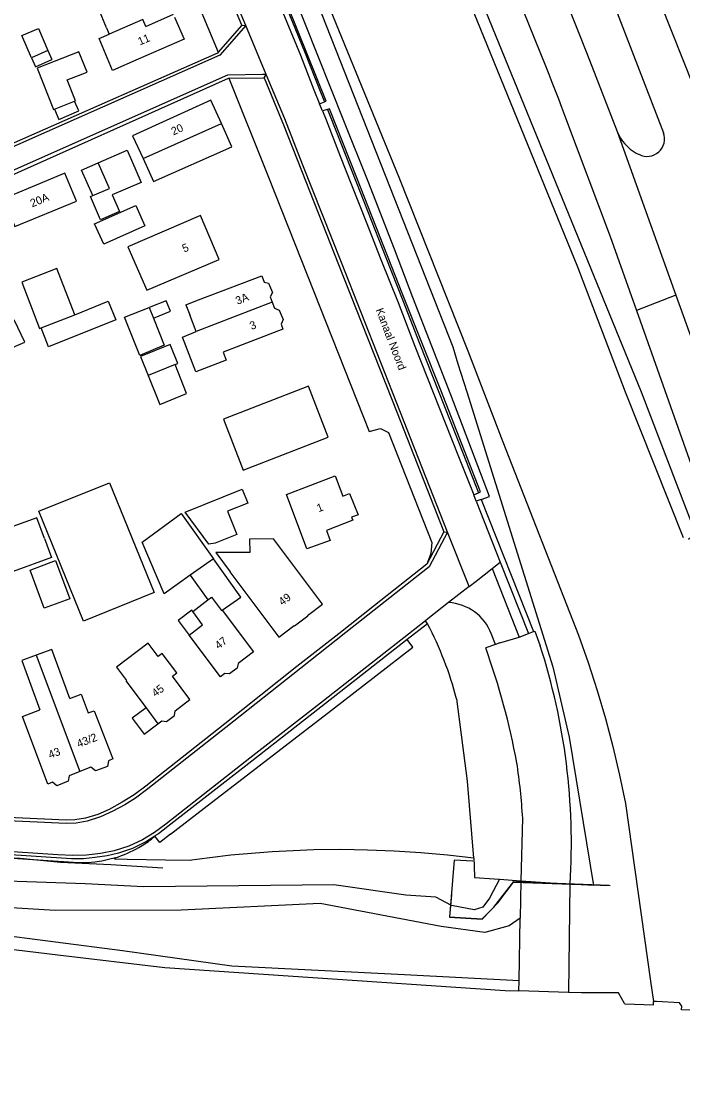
# Model space of a CAD drawing. Extents: x 194485 to 197793, y 468269 to 470822.
# Drawn here: x 195261.5 to 195360.6, y 469144.3 to 469305.5 of the extents above; entities that cross this region are included whole.
import ezdxf

# ---------------------------------------------------------------- set-up
doc = ezdxf.new("R2010")
doc.units = 0
for name, color, linetype in [('BGT begrenzing kruinlijn', 7, 'Continuous'), ('BGT grensvlak begroeid terreindeel', 7, 'Continuous'), ('BGT grensvlak begroeid terreindeel LR', 7, 'Continuous'), ('BGT grensvlak gebouwinstallatie plus 1', 7, 'Continuous'), ('BGT grensvlak onbegroeid terreindeel', 7, 'Continuous'), ('BGT grensvlak overbruggingsdeel plus 1', 7, 'Continuous'), ('BGT grensvlak overig bouwwerk uitbreiding populatie', 7, 'Continuous'), ('BGT grensvlak pand op maaiveld', 7, 'Continuous'), ('BGT grensvlak pand op maaiveld LR', 7, 'Continuous'), ('BGT grensvlak vegetatieobject', 7, 'Continuous'), ('BGT grensvlak waterdeel', 7, 'Continuous'), ('BGT grensvlak wegdeel', 7, 'Continuous'), ('BGT lijnelement scheiding hek', 7, 'Continuous'), ('BGT tekst huisnummerreeks', 7, 'Continuous'), ('BGT tekst openbare ruimte label weg', 7, 'Continuous')]:
    doc.layers.add(name, color=color, linetype=linetype)

msp = doc.modelspace()

# ---------------------------------------------------------------- linework, layer by layer
at = {"layer": 'BGT begrenzing kruinlijn'}
msp.add_lwpolyline([(195333.17, 469176.92), (195331.68, 469174.1), (195330.67, 469172.73), (195329.38, 469172.32), (195325.94, 469172.96), (195323.63, 469174.22), (195319.11, 469174.55), (195308.33, 469176.06), (195279.82, 469175.77), (195271.02, 469176.24), (195250.48, 469176.91), (195218.26, 469179.64), (195172.02, 469183.73), (195139.62, 469186.43), (195110.38, 469187.78), (195083.73, 469188.2), (195047.24, 469190.12), (195024.68, 469191.98), (195021.62, 469193.6)], dxfattribs=at)
at = {"layer": 'BGT grensvlak begroeid terreindeel'}
for p, q in [((195269.27, 469179.41), (195145.74, 469187.55)), ((195333.17, 469176.92), (195336.35, 469176.7))]:
    msp.add_line(p, q, dxfattribs=at)
for points in [[(195249.52, 469422.51), (195254.02, 469415.15), (195263.96, 469398.93), (195268.08, 469392.21), (195276.98, 469375.91), (195284.84, 469359.67), (195304.44, 469311.84), (195326.14, 469256.74), (195326.93, 469254.23), (195328.26, 469250), (195341.19, 469208.79), (195343.63, 469198.23), (195347.26, 469175.96), (195343.77, 469176.2)], [(195275.54, 469180.15), (195274.52, 469179.86), (195273.49, 469179.65), (195272.44, 469179.49), (195271.39, 469179.4), (195270.33, 469179.37), (195269.27, 469179.41)], [(195286.62, 469179.73), (195283.08, 469179.8), (195277.33, 469179.9), (195275.42, 469179.94), (195275.54, 469180.15)], [(195305.33, 469181.31), (195302.2, 469181.2), (195299.08, 469181.03), (195295.95, 469180.8), (195292.84, 469180.51), (195289.73, 469180.15), (195286.62, 469179.73)], [(195329.33, 469180.06), (195325.34, 469180.52), (195321.35, 469180.88), (195317.35, 469181.15), (195313.35, 469181.3), (195309.34, 469181.36), (195305.33, 469181.31)], [(195329.33, 469180.06), (195329.36, 469178.93), (195329.44, 469177.17), (195332.35, 469176.97), (195333.17, 469176.92)]]:
    msp.add_lwpolyline(points, dxfattribs=at)
at = {"layer": 'BGT grensvlak begroeid terreindeel LR'}
msp.add_line((195280.95, 469182.93), (195281.47, 469183.4), dxfattribs=at)
for points in [[(195230.64, 469478.15), (195238.04, 469470.16), (195245.24, 469462.38), (195250.08, 469456.71), (195257.38, 469448.07), (195272.68, 469426.93), (195291.77, 469397.28), (195298.55, 469383.89), (195299.68, 469381.45), (195303.16, 469373.94), (195306.08, 469367.63), (195317.89, 469339.41), (195320.66, 469332.62), (195354.4, 469250), (195362.58, 469228.77), (195361.51, 469227.88)], [(195329.33, 469180.06), (195328.34, 469191.65), (195326.74, 469203.97)]]:
    msp.add_lwpolyline(points, dxfattribs=at)
for centre, radius, start, end in [((195274.31, 469190.16), 54.21, 14.7543, 27.5622), ((195270.44, 469196.67), 17.29, 287.1559, 299.8436), ((195270.4, 469196.75), 17.39, 299.8457, 307.3814)]:
    msp.add_arc(centre, radius, start, end, dxfattribs=at)
at = {"layer": 'BGT grensvlak gebouwinstallatie plus 1'}
for p, q in [((195265.43, 469301.17), (195266.01, 469299.82)), ((195269.44, 469261.56), (195274.45, 469263.59)), ((195274.45, 469263.59), (195275.61, 469260.8)), ((195275.61, 469260.8), (195265.53, 469256.75)), ((195265.53, 469256.75), (195264.4, 469259.61)), ((195286.78, 469222.53), (195289.43, 469218.81)), ((195280.15, 469202.6), (195278.08, 469201.05)), ((195278.08, 469201.05), (195279.86, 469198.67)), ((195279.86, 469198.67), (195281.93, 469200.21))]:
    msp.add_line(p, q, dxfattribs=at)
for points in [[(195262.95, 469300.11), (195263.53, 469298.76), (195266.01, 469299.82)], [(195266.4, 469292.4), (195267.07, 469290.86), (195270.04, 469292.16), (195269.42, 469293.58)], [(195272.14, 469279.43), (195270.48, 469283.27), (195272.98, 469284.35)], [(195284.49, 469254.09), (195284.9, 469254.25), (195283.75, 469257.11), (195279.31, 469255.33), (195280.46, 469252.47)], [(195285.99, 469231.96), (195294.56, 469235.41), (195295.41, 469233.32), (195292.38, 469232.13), (195293.75, 469228.64), (195290.51, 469227.31), (195289.56, 469227.15), (195285.99, 469231.96)], [(195291.57, 469217.26), (195294.34, 469219.24), (195290.24, 469224.99)], [(195266.57, 469224.7), (195268.71, 469218.98), (195264.88, 469217.55), (195262.74, 469223.27), (195266.57, 469224.7)], [(195287.14, 469217.07), (195287, 469217.26), (195284.96, 469215.71), (195286.61, 469213.54)]]:
    msp.add_lwpolyline(points, dxfattribs=at)
at = {"layer": 'BGT grensvlak onbegroeid terreindeel'}
for points in [[(195277.66, 469332.39), (195279.61, 469327.91), (195282.53, 469320.97), (195285.35, 469314.28), (195287.86, 469308.33), (195290.98, 469300.92)], [(195292.54, 469297.03), (195298.41, 469282.44), (195302.49, 469272.09), (195313.61, 469244.08), (195315.3, 469244.52), (195316.49, 469243.92), (195322.99, 469227.43), (195322.84, 469225.79), (195322.27, 469224.15)], [(195336.26, 469171.07), (195334.6, 469169.94), (195330.96, 469168.94), (195324.39, 469169.84), (195306.28, 469173.3), (195285.39, 469172.29), (195266.49, 469172.21), (195242.61, 469173.69), (195217.64, 469175.65), (195191.44, 469178.72), (195175.95, 469179.92), (195158.29, 469182.07), (195146.14, 469183.55), (195135.37, 469183.77), (195129.51, 469183.87)], [(195336.11, 469161.69), (195318.89, 469162.6), (195293.02, 469163.89), (195276.63, 469166.21), (195256.46, 469168.77), (195245.24, 469170.07), (195243.81, 469170.16), (195230.31, 469171.25), (195224.23, 469171.64), (195215.36, 469172.48), (195208.35, 469172.93), (195181.26, 469175.57), (195174.18, 469176.35), (195167.76, 469177.15), (195162.5, 469177.71), (195150.36, 469179.4), (195142.78, 469179.86), (195129.29, 469179.89)], [(195351.93, 469158.31), (195351.96, 469158.26), (195356.25, 469158.08), (195356.28, 469158.59)], [(195360.49, 469157.36), (195360.51, 469157.91), (195360.17, 469158.4), (195356.71, 469158.57), (195356.28, 469158.59)]]:
    msp.add_lwpolyline(points, dxfattribs=at)
at = {"layer": 'BGT grensvlak overbruggingsdeel plus 1'}
msp.add_line((195368.91, 469156.95), (195360.49, 469157.36), dxfattribs=at)
at = {"layer": 'BGT grensvlak overig bouwwerk uitbreiding populatie'}
for p, q in [((195283.16, 469263.67), (195280.62, 469262.66)), ((195283.79, 469262.1), (195283.16, 469263.67)), ((195281.25, 469261.08), (195283.79, 469262.1))]:
    msp.add_line(p, q, dxfattribs=at)
at = {"layer": 'BGT grensvlak pand op maaiveld'}
for p, q in [((195274.19, 469304.59), (195273.04, 469307.38)), ((195261.52, 469303.44), (195264.01, 469304.51)), ((195264.01, 469304.51), (195265.43, 469301.17)), ((195274.19, 469304.59), (195274.61, 469303.64)), ((195262.95, 469300.11), (195261.52, 469303.44)), ((195265.43, 469301.17), (195262.95, 469300.11)), ((195266.4, 469292.4), (195269.42, 469293.58)), ((195266.24, 469292.34), (195266.4, 469292.4)), ((195286.11, 469263.08), (195288.02, 469263.81)), ((195280.62, 469262.66), (195281.25, 469261.08)), ((195286.11, 469263.08), (195286.69, 469261.56)), ((195264.4, 469259.61), (195269.44, 469261.56)), ((195281.25, 469261.08), (195282.87, 469257)), ((195287.68, 469259.04), (195286.69, 469261.56)), ((195264.17, 469259.52), (195264.4, 469259.61)), ((195300.67, 469259.4), (195291.69, 469255.95)), ((195282.87, 469257), (195279.21, 469255.48)), ((195284.49, 469254.09), (195280.46, 469252.47)), ((195285.41, 469231.78), (195290.24, 469224.99)), ((195290.24, 469224.99), (195286.78, 469222.53)), ((195294.23, 469225.93), (195290.61, 469225.9)), ((195287.14, 469217.07), (195289.43, 469218.81)), ((195280.15, 469202.6), (195281.93, 469200.21))]:
    msp.add_line(p, q, dxfattribs=at)
for points in [[(195284.43, 469306.17), (195285.87, 469302.9), (195278.97, 469299.89)], [(195278.97, 469299.89), (195275.13, 469298.21), (195273.12, 469302.98), (195274.61, 469303.64)], [(195269.42, 469293.58), (195269.56, 469293.64), (195268.33, 469296.78), (195271.29, 469297.93), (195270.08, 469301.01), (195263.81, 469298.54), (195266.24, 469292.34)], [(195291.44, 469290.24), (195289.87, 469293.74), (195278.12, 469288.42), (195279.69, 469284.98)], [(195279.69, 469284.98), (195281.27, 469281.54), (195293.02, 469286.74), (195291.44, 469290.24)], [(195272.98, 469284.35), (195277.32, 469286.23), (195279.39, 469281.42), (195275.05, 469279.55), (195276.14, 469277.05), (195273.29, 469275.82), (195271.8, 469279.28), (195272.14, 469279.43)], [(195272.14, 469279.43), (195274.64, 469280.51), (195272.98, 469284.35)], [(195267.97, 469282.78), (195258.73, 469278.95), (195260.45, 469274.79), (195269.69, 469278.62), (195267.97, 469282.78)], [(195272.43, 469275.22), (195278.59, 469277.95), (195279.95, 469274.88), (195273.8, 469272.15), (195272.43, 469275.22)], [(195277.39, 469271.77), (195280.26, 469265.23), (195291.1, 469269.86), (195288.32, 469276.45), (195277.39, 469271.77)], [(195269.44, 469261.56), (195266.76, 469268.48), (195261.49, 469266.44), (195264.17, 469259.52)], [(195288.02, 469263.81), (195297.52, 469267.42), (195297.87, 469266.46), (195298.52, 469266.31), (195299.13, 469264.88), (195298.78, 469264.23), (195299.08, 469263.48)], [(195279.21, 469255.48), (195276.93, 469261.19), (195280.62, 469262.66)], [(195299.08, 469263.48), (195299.43, 469262.58), (195300.12, 469262.27), (195300.71, 469260.87), (195300.42, 469260.16), (195300.67, 469259.4)], [(195259.4, 469256.37), (195261.93, 469257.47), (195260.36, 469260.8)], [(195291.69, 469255.95), (195292.15, 469254.77), (195287.63, 469253.01), (195285.6, 469258.22), (195287.68, 469259.04)], [(195280.46, 469252.47), (195282.2, 469248.12), (195286.23, 469249.74), (195284.49, 469254.09)], [(195291.76, 469245.91), (195294.71, 469238.27), (195307.48, 469243.21), (195304.52, 469250.84), (195291.76, 469245.91)], [(195264.06, 469232.14), (195274.67, 469236.38), (195281.38, 469219.93), (195270.77, 469215.64), (195264.06, 469232.14)], [(195301.2, 469234.62), (195308.51, 469237.42), (195309.65, 469234.35), (195310.67, 469234.77), (195311.94, 469231.58), (195310.95, 469231.24), (195311.14, 469230.76), (195307.21, 469229.24), (195307.74, 469227.73), (195304.25, 469226.47), (195301.2, 469234.62)], [(195286.78, 469222.53), (195282.85, 469219.73), (195279.54, 469227.46), (195285.41, 469231.78)], [(195264.9, 469228.01), (195263.77, 469231.14), (195257.07, 469228.7)], [(195264.9, 469228.01), (195265.94, 469225.16), (195260.22, 469223.08)], [(195290.61, 469225.9), (195292.74, 469223.03), (195292.7, 469223), (195300.05, 469213.23), (195302.37, 469214.98), (195302.41, 469214.91), (195304.39, 469216.4), (195304.34, 469216.47), (195306.63, 469218.19), (195299.27, 469227.98), (195295.67, 469227.92), (195295.7, 469225.94), (195294.23, 469225.93)], [(195289.43, 469218.81), (195289.97, 469219.21), (195291.48, 469217.21), (195291.57, 469217.27), (195291.57, 469217.26)], [(195291.57, 469217.26), (195296.26, 469211.04), (195293.94, 469209.29), (195293.83, 469208.58), (195292.67, 469207.7), (195291.95, 469207.79), (195291.3, 469207.29), (195286.61, 469213.54)], [(195286.61, 469213.54), (195288.63, 469215.07), (195287.14, 469217.07)], [(195281.93, 469200.21), (195282.53, 469200.67), (195283.23, 469200.57), (195284.41, 469201.47), (195284.5, 469202.16), (195286.72, 469203.85), (195284.12, 469207.38), (195284.75, 469207.85), (195282.57, 469210.78), (195281.95, 469210.31), (195280.46, 469212.32), (195275.71, 469208.74)], [(195263.65, 469210.51), (195261.5, 469209.72), (195264.2, 469202.3)], [(195268.7, 469204.01), (195266.02, 469211.37), (195263.65, 469210.51)], [(195275.71, 469208.74), (195277.21, 469206.73), (195277.12, 469206.66), (195280.15, 469202.6)], [(195268.7, 469204.01), (195270.4, 469204.66), (195271.45, 469201.86), (195272.36, 469202.18), (195275.18, 469194.97), (195274.53, 469194.66), (195274.35, 469193.84), (195272.55, 469193.2), (195271.88, 469193.72), (195270.23, 469193.08)], [(195270.23, 469193.08), (195268.59, 469192.44), (195268.46, 469191.62), (195266.77, 469190.94), (195266.11, 469191.49), (195265.42, 469191.18), (195261.62, 469201.3), (195264.2, 469202.3)]]:
    msp.add_lwpolyline(points, dxfattribs=at)
at = {"layer": 'BGT grensvlak pand op maaiveld LR'}
for p, q in [((195279.64, 469305.85), (195274.61, 469303.64)), ((195280.1, 469304.81), (195279.64, 469305.85)), ((195280.1, 469304.81), (195284.28, 469306.65)), ((195279.69, 469284.98), (195291.44, 469290.24)), ((195299.08, 469263.48), (195287.68, 469259.04)), ((195263.65, 469210.51), (195270.23, 469193.08))]:
    msp.add_line(p, q, dxfattribs=at)
at = {"layer": 'BGT grensvlak vegetatieobject'}
for p, q in [((195330.43, 469233.87), (195338.27, 469214.05)), ((195333.29, 469224.47), (195337.52, 469213.77)), ((195288.88, 469187.6), (195301.02, 469196.94)), ((195283.8, 469183.68), (195288.88, 469187.6))]:
    msp.add_line(p, q, dxfattribs=at)
for points in [[(195299.82, 469311.02), (195300.55, 469309.29), (195304.03, 469300.77), (195306.07, 469295.58), (195306.91, 469293.5)], [(195307.36, 469292.37), (195307.88, 469291.08), (195310, 469285.66), (195311.72, 469281.34), (195313.92, 469275.77), (195316.12, 469270.17), (195318.68, 469263.7), (195321.21, 469257.14), (195327.68, 469240.85), (195330.04, 469234.87)], [(195301.02, 469196.94), (195307.97, 469202.29), (195314.61, 469207.4), (195320.18, 469211.71), (195319.31, 469212.85)], [(195283.8, 469183.68), (195282.2, 469182.45), (195281.47, 469183.4)]]:
    msp.add_lwpolyline(points, dxfattribs=at)
at = {"layer": 'BGT grensvlak waterdeel'}
for points in [[(195297.94, 469382.06), (195300.96, 469375.28), (195310.75, 469352.34), (195344.87, 469268.75), (195352.02, 469250), (195360.73, 469228.16)], [(195297.94, 469382.06), (195300.96, 469375.28), (195310.75, 469352.34), (195344.87, 469268.75), (195352.02, 469250), (195360.73, 469228.16)], [(195279.93, 469373.84), (195286.57, 469359.56), (195296.2, 469336.38), (195307.3, 469308.43), (195318.05, 469282.21), (195328.42, 469256.17), (195333.66, 469242.5), (195345.03, 469213.53)], [(195345.03, 469213.53), (195346.48, 469209.41), (195347.82, 469205.24), (195349.05, 469201.04), (195350.17, 469196.81), (195351.17, 469192.55), (195352.06, 469188.27)], [(195352.06, 469188.27), (195355.8, 469161.65), (195356.28, 469158.59)]]:
    msp.add_lwpolyline(points, dxfattribs=at)
at = {"layer": 'BGT grensvlak wegdeel'}
for p, q in [((195312.27, 469368.3), (195340.06, 469298.87)), ((195357.3, 469308.25), (195362.29, 469295.8)), ((195294.51, 469305), (195290.98, 469300.92)), ((195294.51, 469305), (195295.09, 469304.96)), ((195298.18, 469297.6), (195295.09, 469304.96)), ((195297.84, 469297.08), (195298.18, 469297.6)), ((195292.54, 469297.03), (195297.84, 469297.08)), ((195306.17, 469293.18), (195306.91, 469293.5)), ((195306.59, 469292.14), (195306.17, 469293.18)), ((195307.36, 469292.37), (195306.59, 469292.14)), ((195342.93, 469291.49), (195349.77, 469273.29)), ((195350.81, 469289.04), (195359.63, 469264.5)), ((195353.67, 469285.78), (195354.11, 469285.62)), ((195349.77, 469273.29), (195353.71, 469262.19)), ((195359.63, 469264.5), (195353.71, 469262.19)), ((195359.63, 469264.5), (195362.28, 469257.14)), ((195329.31, 469234.54), (195330.04, 469234.87)), ((195329.68, 469233.6), (195329.31, 469234.54)), ((195330.43, 469233.87), (195329.68, 469233.6)), ((195329.68, 469233.6), (195333.29, 469224.47)), ((195324.81, 469229.01), (195322.27, 469224.15)), ((195324.81, 469229.01), (195325.37, 469228.98)), ((195328.59, 469220.8), (195325.37, 469228.98)), ((195329.65, 469221.63), (195332.08, 469223.53)), ((195332.08, 469223.53), (195333.29, 469224.47)), ((195332.08, 469223.53), (195336.13, 469213.24)), ((195328.59, 469220.8), (195325.52, 469218.4)), ((195328.59, 469220.8), (195329.65, 469221.63)), ((195325.52, 469218.4), (195322.41, 469215.95)), ((195322.04, 469215.67), (195313.26, 469208.75)), ((195322.41, 469215.95), (195322.04, 469215.67)), ((195322.37, 469215.24), (195322.04, 469215.67)), ((195322.37, 469215.24), (195319.31, 469212.85)), ((195332.56, 469212.13), (195331.93, 469213.75)), ((195336.13, 469213.24), (195337.52, 469213.77)), ((195337.52, 469213.77), (195338.27, 469214.05)), ((195338.27, 469214.05), (195338.46, 469214.12)), ((195338.46, 469214.12), (195339.28, 469211.91)), ((195332.56, 469212.13), (195331.1, 469211.61)), ((195333.24, 469212.38), (195332.56, 469212.13)), ((195333.24, 469212.38), (195336.13, 469213.24)), ((195313.26, 469208.75), (195306.75, 469203.68)), ((195306.75, 469203.68), (195295.7, 469195.08)), ((195295.7, 469195.08), (195283.1, 469185.2)), ((195283.1, 469185.2), (195281.4, 469183.93)), ((195336.64, 469186.08), (195336.35, 469176.7)), ((195281.4, 469183.93), (195279.63, 469182.83)), ((195266.9, 469180.58), (195246.93, 469181.88)), ((195277.57, 469181.88), (195275.37, 469181.17)), ((195279.63, 469182.83), (195277.57, 469181.88)), ((195269.14, 469180.46), (195266.9, 469180.58)), ((195271.23, 469180.54), (195269.14, 469180.46)), ((195273.33, 469180.79), (195271.23, 469180.54)), ((195275.37, 469181.17), (195273.33, 469180.79)), ((195336.35, 469176.7), (195336.26, 469171.07)), ((195336.35, 469176.7), (195343.77, 469176.2)), ((195343.55, 469159.94), (195343.77, 469176.2)), ((195336.11, 469161.69), (195336.26, 469171.07)), ((195336.07, 469160.19), (195336.11, 469161.69))]:
    msp.add_line(p, q, dxfattribs=at)
for points in [[(195319.02, 469386.35), (195350.2, 469308.38), (195357.77, 469288.86)], [(195313.03, 469383.96), (195345.27, 469303.3), (195346.69, 469299.73), (195350.81, 469289.04)], [(195295.09, 469304.96), (195288.53, 469320.61), (195283.39, 469332.79), (195283.03, 469333.58)], [(195294.51, 469305), (195288.52, 469319.28), (195282.93, 469332.64)], [(195299.08, 469310.72), (195299.81, 469308.98), (195303.29, 469300.48), (195305.33, 469295.28), (195306.17, 469293.18)], [(195306.91, 469293.5), (195307.17, 469293.61), (195300.1, 469311.14), (195299.82, 469311.02)], [(195330.43, 469233.87), (195331.66, 469234.3), (195325.86, 469249.57), (195320.14, 469264.17), (195317.39, 469271.39), (195313.46, 469281.54), (195309.83, 469290.66), (195301.99, 469310.3)], [(195295.09, 469304.96), (195291.21, 469300.47), (195252.01, 469283.13), (195228.98, 469272.82), (195202.71, 469261.05), (195170.73, 469246.56), (195169.17, 469245.87)], [(195290.98, 469300.92), (195290.88, 469300.81), (195251.8, 469283.59), (195228.8, 469273.28), (195202.48, 469261.46), (195170.57, 469247.05), (195168.96, 469246.37), (195168.4, 469246.18)], [(195298.18, 469297.6), (195297.63, 469297.59), (195292.38, 469297.51), (195254.61, 469280.73), (195230.45, 469269.89), (195204.49, 469258.24), (195169.64, 469242.42), (195168.1, 469241.62)], [(195325.37, 469228.98), (195318.3, 469246.92), (195309.44, 469269.39), (195303.67, 469284.01), (195300.96, 469290.95), (195298.18, 469297.6)], [(195340.06, 469298.87), (195340.55, 469297.64), (195341.04, 469296.42), (195341.52, 469295.19), (195342, 469293.96), (195342.47, 469292.72), (195342.93, 469291.49)], [(195168.58, 469241.38), (195204.76, 469257.79), (195230.45, 469269.32), (195254.69, 469280.16), (195292.5, 469297.03), (195292.54, 469297.03)], [(195297.84, 469297.08), (195300.78, 469290.05), (195303.46, 469283.2), (195309.02, 469269.12), (195317.79, 469246.85), (195324.81, 469229.01)], [(195306.59, 469292.14), (195307.14, 469290.78), (195309.26, 469285.37), (195310.98, 469281.05), (195313.18, 469275.48), (195315.38, 469269.87), (195317.94, 469263.41), (195320.46, 469256.85), (195326.93, 469240.55), (195329.31, 469234.54)], [(195330.04, 469234.87), (195330.33, 469235), (195324.34, 469250.25), (195318.65, 469264.54), (195311.77, 469282.1), (195307.66, 469292.46), (195307.36, 469292.37)], [(195353.71, 469262.19), (195365.01, 469230.3), (195389.86, 469165.31), (195397.88, 469144.34)], [(195325.37, 469228.98), (195322.6, 469223.78), (195310.1, 469213.9), (195303.34, 469208.57), (195292.09, 469199.68), (195280.4, 469190.49), (195278.58, 469189.07), (195276.95, 469188.06), (195275.18, 469187.14), (195273.33, 469186.29), (195271.33, 469185.61), (195269.67, 469185.35), (195268.17, 469185.29), (195244.08, 469186.38), (195223.65, 469187.43), (195191.7, 469189.18), (195188.12, 469189.38), (195185.27, 469189.76)], [(195322.27, 469224.15), (195314.42, 469217.97), (195309.07, 469213.72), (195302.78, 469208.8), (195291.96, 469200.24), (195280.11, 469190.86), (195278.34, 469189.58), (195276.56, 469188.47), (195274.61, 469187.4), (195272.92, 469186.61), (195271.05, 469186.07), (195269.44, 469185.82), (195268.14, 469185.79), (195251.84, 469186.54), (195223.75, 469187.94), (195191.94, 469189.68), (195188.19, 469189.91)], [(195319.31, 469212.85), (195313.52, 469208.33), (195307.05, 469203.28), (195295.99, 469194.61), (195283.43, 469184.83), (195281.99, 469183.73), (195281.57, 469183.46), (195281.47, 469183.4)], [(195281.47, 469183.4), (195280.21, 469182.6), (195278.1, 469181.55), (195275.99, 469180.84), (195274.33, 469180.45), (195272.48, 469180.18), (195270.74, 469180), (195268.95, 469179.98), (195247.71, 469181.36), (195223.78, 469182.89), (195191.63, 469184.97), (195177.62, 469185.93)], [(195151.11, 469176.57), (195172.1, 469175.19), (195189.2, 469173.54), (195229.68, 469170.09), (195266.92, 469165.61), (195282.97, 469163.69), (195334.04, 469160.25), (195336.07, 469160.19)], [(195343.55, 469159.94), (195343.54, 469159.94), (195336.07, 469160.19)], [(195351.93, 469158.31), (195351.04, 469159.9), (195345.47, 469159.88), (195343.55, 469159.94)]]:
    msp.add_lwpolyline(points, dxfattribs=at)
for centre, radius, start, end in [((195357.05, 469291.62), 6.74, 202.4197, 239.9099), ((195355.33, 469287.93), 2.61, 242.0899, 20.9612), ((195325.13, 469211.11), 7.3, 21.2017, 86.866), ((195227.66, 469174.37), 109.94, 10.4924, 19.7963), ((195247.67, 469182.28), 96.28, 356.3805, 17.926), ((195243.9, 469180.52), 92.91, 3.4313, 8.5874)]:
    msp.add_arc(centre, radius, start, end, dxfattribs=at)
at = {"layer": 'BGT lijnelement scheiding hek'}
for points in [[(195021.21, 469186.03), (195021.62, 469193.6), (195066.62, 469191.35), (195077.1, 469190.88), (195086.22, 469190.43), (195101.5, 469189.7), (195113.7, 469188.96), (195127.64, 469188.5), (195146.63, 469187.07), (195215.87, 469182.97), (195223.85, 469182.45), (195239.4, 469181.5), (195255.21, 469180.23), (195261.24, 469180.09), (195267.29, 469179.46), (195274.86, 469179.14), (195282.66, 469178.61)], [(195329.19, 469179.61), (195326.36, 469179.79), (195325.67, 469171.23), (195330.56, 469170.91), (195332.91, 469173.37), (195335.26, 469176.5), (195349.76, 469175.98)], [(195325.96, 469174.6), (195325.68, 469171.26), (195330.58, 469170.99), (195332.31, 469172.72), (195335.34, 469176.56), (195349.61, 469176.01)]]:
    msp.add_lwpolyline(points, dxfattribs=at)

# ---------------------------------------------------------------- texts
at = {"layer": 'BGT tekst huisnummerreeks'}
for s, rotation, p in [('11', 22.8, (195279.21, 469301.94)), ('20', 24.4, (195284.23, 469288.44)), ('20A', 22.5, (195263.06, 469277.66)), ('5', 22.9, (195285.86, 469270.88)), ('3A', 21.5, (195293.84, 469263.05)), ('3', 21.3, (195295.96, 469259.28)), ('1', 21.6, (195306.03, 469231.94)), ('49', 37, (195300.58, 469217.89)), ('47', 37.1, (195291.02, 469211.34)), ('45', 37.2, (195281.55, 469204.19)), ('43/2', 20.9, (195270.01, 469196.63)), ('43', 21.5, (195265.75, 469194.97))]:
    msp.add_text(s, height=1.2, rotation=rotation, dxfattribs=at).set_placement(p)
at = {"layer": 'BGT tekst openbare ruimte label weg'}
msp.add_text('Kanaal Noord', height=1.2, rotation=291, dxfattribs=at).set_placement((195314.57, 469262.3))

doc.saveas('drawing.dxf')
